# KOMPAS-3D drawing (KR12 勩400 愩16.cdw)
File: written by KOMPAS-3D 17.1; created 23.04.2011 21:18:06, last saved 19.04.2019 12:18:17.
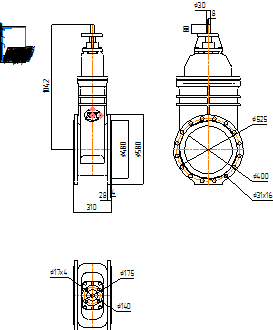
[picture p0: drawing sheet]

Sheet 1: A4, portrait

Title block, sheet 1: name: KR12 Ду400 Ру16; material: Внимание! Данный продукт является объектом авторского права ООО «Торговый Дом АДЛ». / Запрещается изменение, копирование, распространение / (в том числе путем копирования на другие сайты и ресурсы в Интернете) / или любое иное использование информации и объектов без предварительного / согласия правообладателя (ООО «Торговый Дом АДЛ»).; scale: 1:1; sheets: 1; organisation: ООО "Торговый дом АДЛ"; sheet format: A4; stored path: \\adlc.lan\data\АДЛ_ПКД\3D-модели\ADL production\Клиновые задвижки серии KR ГРАНАР\Клиновые задвижки KR12\KOMPAS 2D\KR12 Ду400 Ру16.cdw

Views: Спереди 7, Проекционный вид 8
Dimensions and other numbers on the sheet: 310; 1042; 480; 580; 28; 4; 140; 175; 17; 1:1; 1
